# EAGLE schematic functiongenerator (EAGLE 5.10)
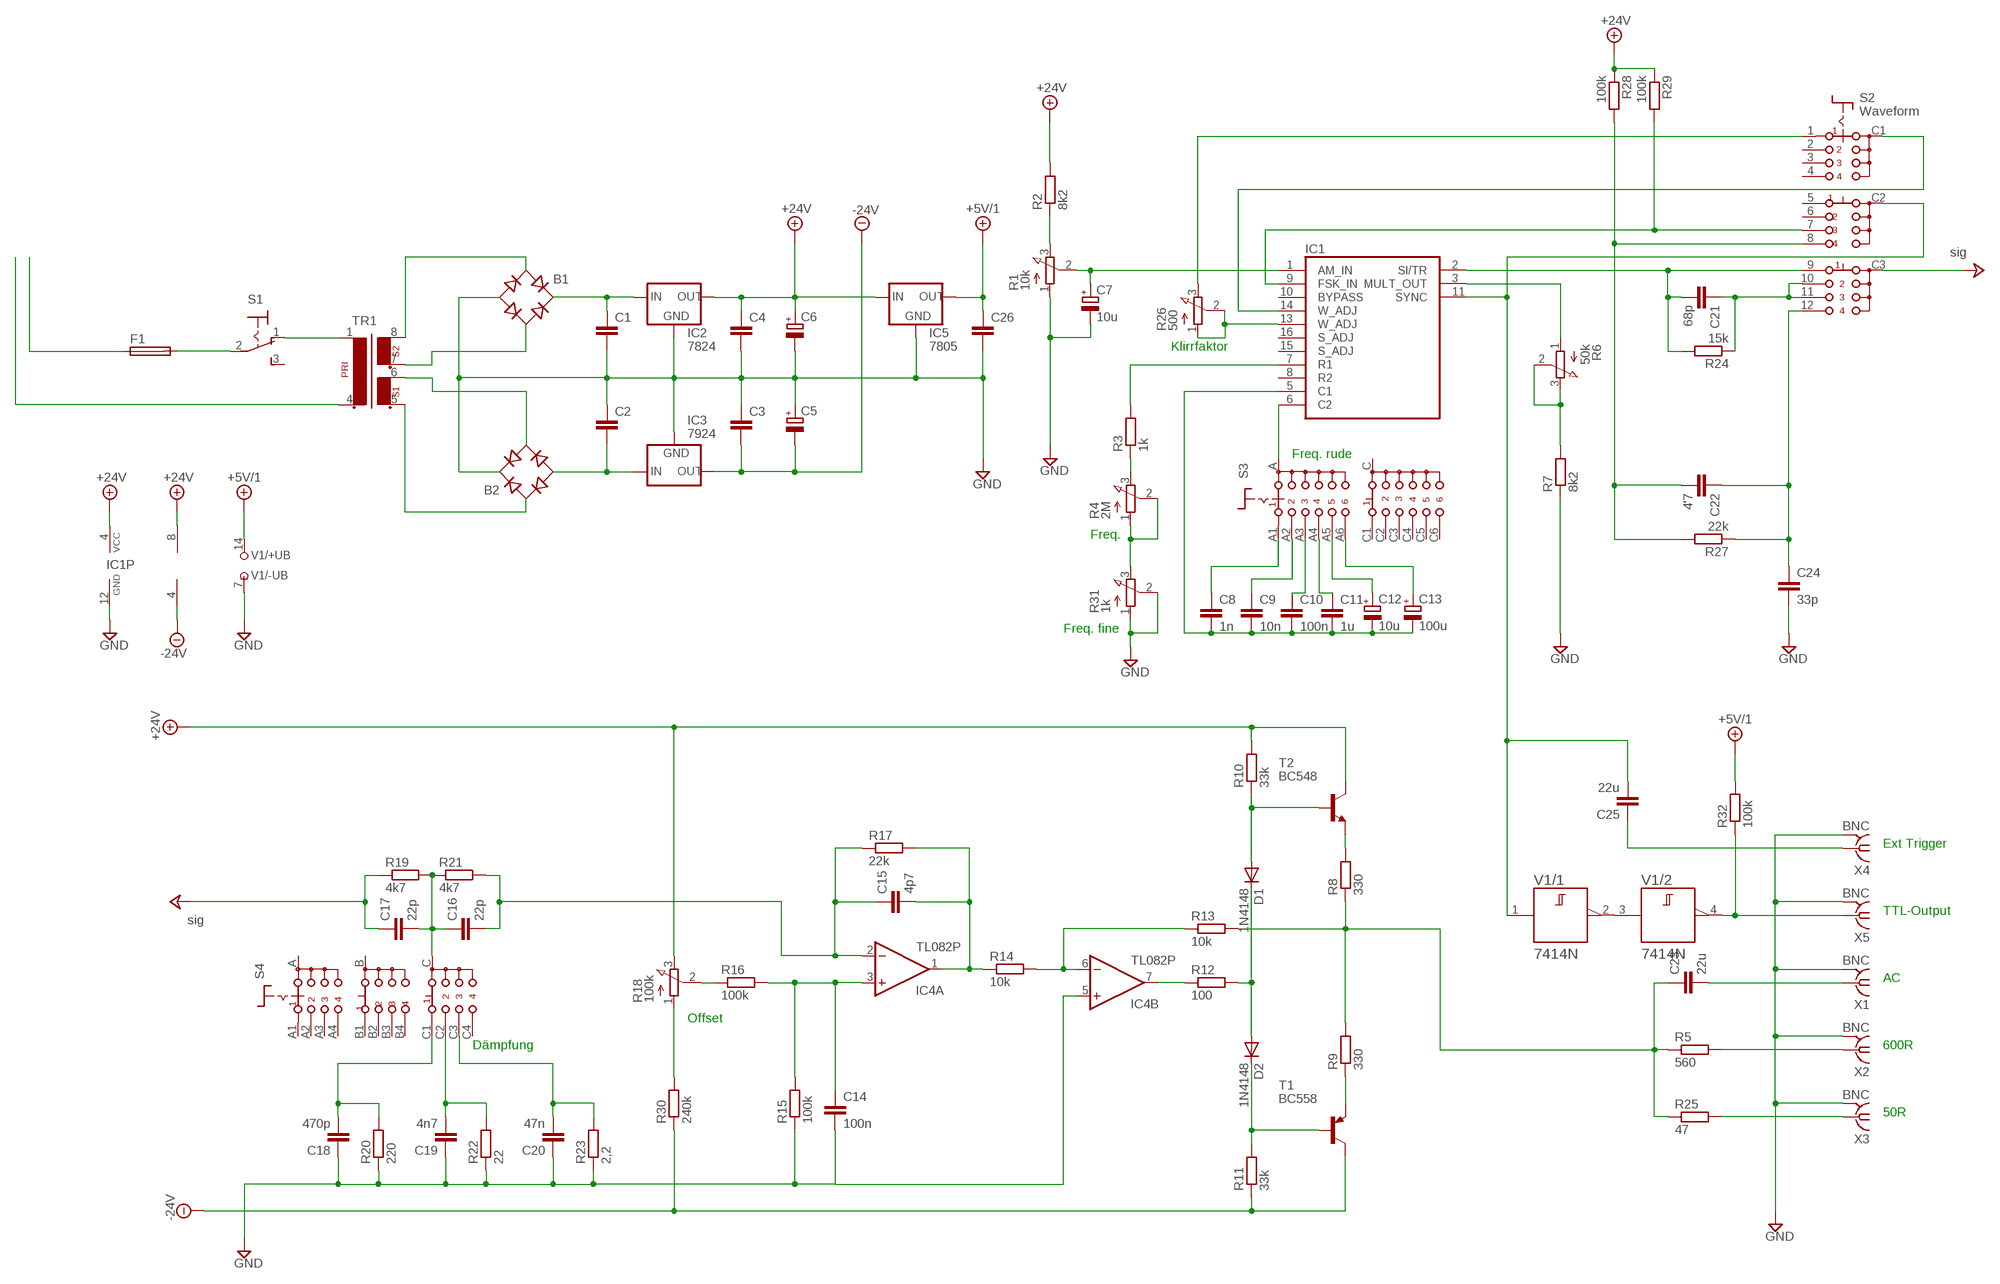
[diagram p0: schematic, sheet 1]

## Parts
B1  B-DIL  [B-DIL]
B2  B-DIL  [B-DIL]
C1  C-EU025-024X044  [C025-024X044]
C2  C-EU025-024X044  [C025-024X044]
C3  C-EU025-024X044  [C025-024X044]
C4  C-EU025-024X044  [C025-024X044]
C5  CPOL-EUE2.5-7  [E2,5-7]
C6  CPOL-EUE2.5-7  [E2,5-7]
C7  10u  CPOL-EUE2-5  [E2-5]
C8  1n  C-EU025-030X050  [C025-030X050]
C9  10n  C-EU025-030X050  [C025-030X050]
C10  100n  C-EU025-030X050  [C025-030X050]
C11  1u  C-EU025-030X050  [C025-030X050]
C12  10u  CPOL-EUE2.5-7  [E2,5-7]
C13  100u  CPOL-EUE2.5-7  [E2,5-7]
C14  100n  C-EU025-024X044  [C025-024X044]
C15  4p7  C-EU025-024X044  [C025-024X044]
C16  22p  C-EU025-024X044  [C025-024X044]
C17  22p  C-EU025-024X044  [C025-024X044]
C18  470p  C-EU025-024X044  [C025-024X044]
C19  4n7  C-EU025-024X044  [C025-024X044]
C20  47n  C-EU025-024X044  [C025-024X044]
C21  68p  C-EU025-024X044  [C025-024X044]
C22  4'7  C-EU025-024X044  [C025-024X044]
C23  22u  C-EU025-024X044  [C025-024X044]
C24  33p  C-EU025-024X044  [C025-024X044]
C25  22u  C-EU025-024X044  [C025-024X044]
C26  C-EU025-024X044  [C025-024X044]
D1  1N4148  1N4148DO35-10  [DO35-10]
D2  1N4148  1N4148DO35-10  [DO35-10]
F1  SH22,5A  [SH22,5A]
IC1  XR-2206  [DIL16]
IC2  7824  78XXL  [78XXL]
IC3  7924  79XXL  [79XXL]
IC4  TL082P  [DIL08]
IC5  7805  78XXL  [78XXL]
R1  10k  3RP/1610N  [3RP/1610N]
R2  8k2  R-EU_0207/10  [0207/10]
R3  1k  R-EU_0207/10  [0207/10]
R4  2M  3RP/1610N  [3RP/1610N]
R5  560  R-EU_0207/10  [0207/10]
R6  50k  3RP/1610N  [3RP/1610N]
R7  8k2  R-EU_0207/10  [0207/10]
R8  330  R-EU_0207/10  [0207/10]
R9  330  R-EU_0207/10  [0207/10]
R10  33k  R-EU_0207/10  [0207/10]
R11  33k  R-EU_0207/10  [0207/10]
R12  100  R-EU_0207/10  [0207/10]
R13  10k  R-EU_0207/10  [0207/10]
R14  10k  R-EU_0207/10  [0207/10]
R15  100k  R-EU_0207/10  [0207/10]
R16  100k  R-EU_0207/10  [0207/10]
R17  22k  R-EU_0207/10  [0207/10]
R18  100k  3RP/1610N  [3RP/1610N]
R19  4k7  R-EU_0207/10  [0207/10]
R20  220  R-EU_0207/10  [0207/10]
R21  4k7  R-EU_0207/10  [0207/10]
R22  22  R-EU_0207/10  [0207/10]
R23  2,2  R-EU_0207/10  [0207/10]
R24  15k  R-EU_0207/10  [0207/10]
R25  47  R-EU_0207/10  [0207/10]
R26  500  3RP/1610N  [3RP/1610N]
R27  22k  R-EU_0207/10  [0207/10]
R28  100k  R-EU_0207/10  [0207/10]
R29  100k  R-EU_0207/10  [0207/10]
R30  240k  R-EU_0207/10  [0207/10]
R31  1k  3RP/1610N  [3RP/1610N]
R32  100k  R-EU_0207/10  [0207/10]
S1  320-916  [320-916]
S2  Waveform  50-3POLE30  [50-3POLE30]
S3  CK102X06  [CK102X06]
S4  CK103X04  [CK103X04]
T1  BC558  BD244  [TO220]
T2  BC548  BD243  [TO220]
TR1  EE20-2  [EE20-2]
V1  7414N  [DIL14]
X1  BNC  BU-SMA-G  [BU-SMA-G]
X2  BNC  BU-SMA-G  [BU-SMA-G]
X3  BNC  BU-SMA-G  [BU-SMA-G]
X4  BNC  BU-SMA-G  [BU-SMA-G]
X5  BNC  BU-SMA-G  [BU-SMA-G]

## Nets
+5V/1: C26.1 IC5.OUT R32.2 V1.14(/+UB:+UB)
+24V: C4.1 C6.+ C17.1 IC1.4(VCC) IC2.OUT IC4.8(P:V+) IC5.IN R2.2 R10.2 R18.3(E) R19.1 R28.1 R29.1 S2.C3(C) T2.2(C) ; supply symbol labelled sig
-24V: C3.2 C5.- IC3.OUT IC4.4(P:V-) R11.1 R30.1 T1.2(C)
GND: B1.- B2.+ C1.2 C2.1 C3.1 C4.2 C5.+ C6.- C7.- C14.2 C18.1 C19.1 C20.1 C24.2 C26.2 IC1.12(GND) IC2.GND IC3.GND IC4.5(B:+IN) IC5.GND R1.1(A) R7.1 R15.1 R20.1 R22.1 R23.1 R31.1(A) R31.2(S) V1.7(/-UB:-UB)
N$1: B1.+ C1.1 IC2.IN
N$2: B2.- C2.2 IC3.IN
N$3: S1.1(O) TR1.1
N$4: TR1.4
N$5: R1.3(E) R2.1
N$6: B1.AC1 TR1.8
N$7: C7.+ IC1.1(AM_IN) R1.2(S)
N$8: D2.C R11.2 T1.1(B)
N$9: B2.AC2 TR1.6
N$10: B1.AC2 TR1.7
N$11: B2.AC1 TR1.5
N$12: F1.2 S1.2(P)
N$13: F1.1
N$14: IC1.6(C2) S3.A
N$15: C8.1 S3.A1
N$16: C9.1 S3.A2
N$17: C10.1 S3.A3
N$18: C11.1 S3.A4
N$19: C12.+ S3.A5
N$20: C13.+ S3.A6
N$21: C8.2 C9.2 C10.2 C11.2 C12.- C13.- IC1.5(C1)
N$22: IC1.7(R1) R3.2
N$23: R3.1 R4.3(E)
N$24: R9.1 T1.3(E)
N$25: C25.2 IC1.11(SYNC) S2.C2(B) V1.1(/1:A)
N$26: IC1.3(MULT_OUT) R6.1(A)
N$27: R6.2(S) R6.3(E) R7.2
N$28: D1.A R10.1 T2.1(B)
N$29: D1.C D2.A R12.2
N$30: C23.1 R5.1 R8.1 R9.2 R13.2 R25.1
N$31: R8.2 T2.3(E)
N$32: R18.1(A) R30.2
N$33: IC4.7(B:OUT) R12.1
N$34: IC4.6(B:-IN) R13.1 R14.2
N$35: C22.2 R27.2 R28.2 S2.8(B4)
N$36: C15.2 IC4.1(A:OUT) R14.1 R17.2
N$37: C15.1 C16.2 IC4.2(A:-IN) R17.1 R21.2
N$38: C14.1 IC4.3(A:+IN) R15.2 R16.2
N$39: R16.1 R18.2(S)
N$40: C18.2 R20.2 S4.C1
N$41: C16.1 C17.2 R19.2 R21.1 S4.C
N$42: C19.2 R22.2 S4.C2
N$43: C21.2 IC1.2(SI/TR) R24.2 S2.9(C1)
N$44: C20.2 R23.2 S4.C3
N$45: C21.1 R24.1 S2.10(C2) S2.11(C3)
N$46: C22.1 C24.1 R27.1 S2.12(C4)
N$47: R26.3(E) S2.1(A1)
N$48: X1.2(GND) X2.2(GND) X3.2(GND) X4.2(GND) X5.2(GND) ; supply symbol labelled GND
N$49: C23.2 X1.1
N$50: R5.2 X2.1
N$51: R25.2 X3.1
N$52: IC1.13(W_ADJ) R26.1(A) R26.2(S)
N$53: IC1.14(W_ADJ) S2.C1(A)
N$54: R4.1(A) R4.2(S) R31.3(E)
N$55: V1.2(/1:Y) V1.3(/2:A)
N$56: IC1.9(FSK_IN) R29.2 S2.7(B3)
N$57: R32.1 V1.4(/2:Y) X5.1
N$58: C25.1 X4.1
Unconnected: IC1.8(R2) IC1.10(BYPASS) IC1.15(S_ADJ) IC1.16(S_ADJ) S1.3(S) S2.2(A2) S2.3(A3) S2.4(A4) S2.5(B1) S2.6(B2) S3.C S3.C1 S3.C2 S3.C3 S3.C4 S3.C5 S3.C6 S4.A S4.A1 S4.A2 S4.A3 S4.A4 S4.B S4.B1 S4.B2 S4.B3 S4.B4 S4.C4 V1.5(/3:A) V1.6(/3:Y) V1.8(/4:Y) V1.9(/4:A) V1.10(/5:Y) V1.11(/5:A) V1.12(/6:Y) V1.13(/6:A)

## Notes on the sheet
- Klirrfaktor
- Freq. rude
- Freq.
- Freq. fine
- Ext Trigger
- TTL-Output
- AC
- Offset
- Dämpfung | 600R
- 50R

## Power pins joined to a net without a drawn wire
GND: X1.3(GND) X1.4(GND) X1.5(GND) X2.3(GND) X2.4(GND) X2.5(GND) X3.3(GND) X3.4(GND) X3.5(GND) X4.3(GND) X4.4(GND) X4.5(GND) X5.3(GND) X5.4(GND) X5.5(GND)

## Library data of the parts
B1 B2 = rectifier:B-DIL: RECTIFIER
C1-C4 C8-C11 C14-C26 = rcl:C-EU: CAPACITOR, European symbol
C5-C7 C12 C13 = rcl:CPOL-EU: POLARIZED CAPACITOR, European symbol
D1 D2 = diode:1N4148: DIODE
F1 = fuse:SH22,5A: FUSE HOLDER
IC1 = exar:XR-2206: Monolithic FUNCTION GENERATOR
IC2 IC5 = v-reg:78XXL: VOLTAGE REGULATOR
IC3 = v-reg:79XXL: VOLTAGE REGULATOR
IC4 = linear:TL082: OP AMP
R1 R4 R6 R18 R26 R31 = pot:3RP/1610N: 16mm Potentiometer one level Source: http://www.alphapotentiometers.net/html/16mm_pot_2.html
R2 R3 R5 R7-R17 R19-R25 R27-R30 R32 = rcl:R-EU_: RESISTOR, European symbol
S1 = switch:320-916: TOGGLE SWITCH distributor RS Components
S2 = switch:50-3POLE30: SERIES 50 Single-Deck Rotary Switches three pole 30° Source: www.grayhill.com .. J-15-21.pdf
S3 = switch:CK102X06: ROTARY SWITCH C&K
S4 = switch:CK103X04: ROTARY SWITCH C&K
T1 = transistor:BD244: PNP TRANSISTOR Source: Motorola Semiconductor, Master Selection Guide Q3/95 SG73 REV 8 page 5.5-5
T2 = transistor:BD243: NPN TRANSISTOR Source: Motorola Semiconductor, Master Selection Guide Q3/95 SG73 REV 8 page 5.5-4
TR1 = trafo:EE20-2: TRANSFORMER 1 primary winding, 2 secondary windings ERA
V1 = 74ttl-din:74*14: Hex schmitt trigger INVERTER
X1-X5 = con-coax:BU-SMA-G: FEMALE SMA CONNECTOR Radiall distributor RS 193-9117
